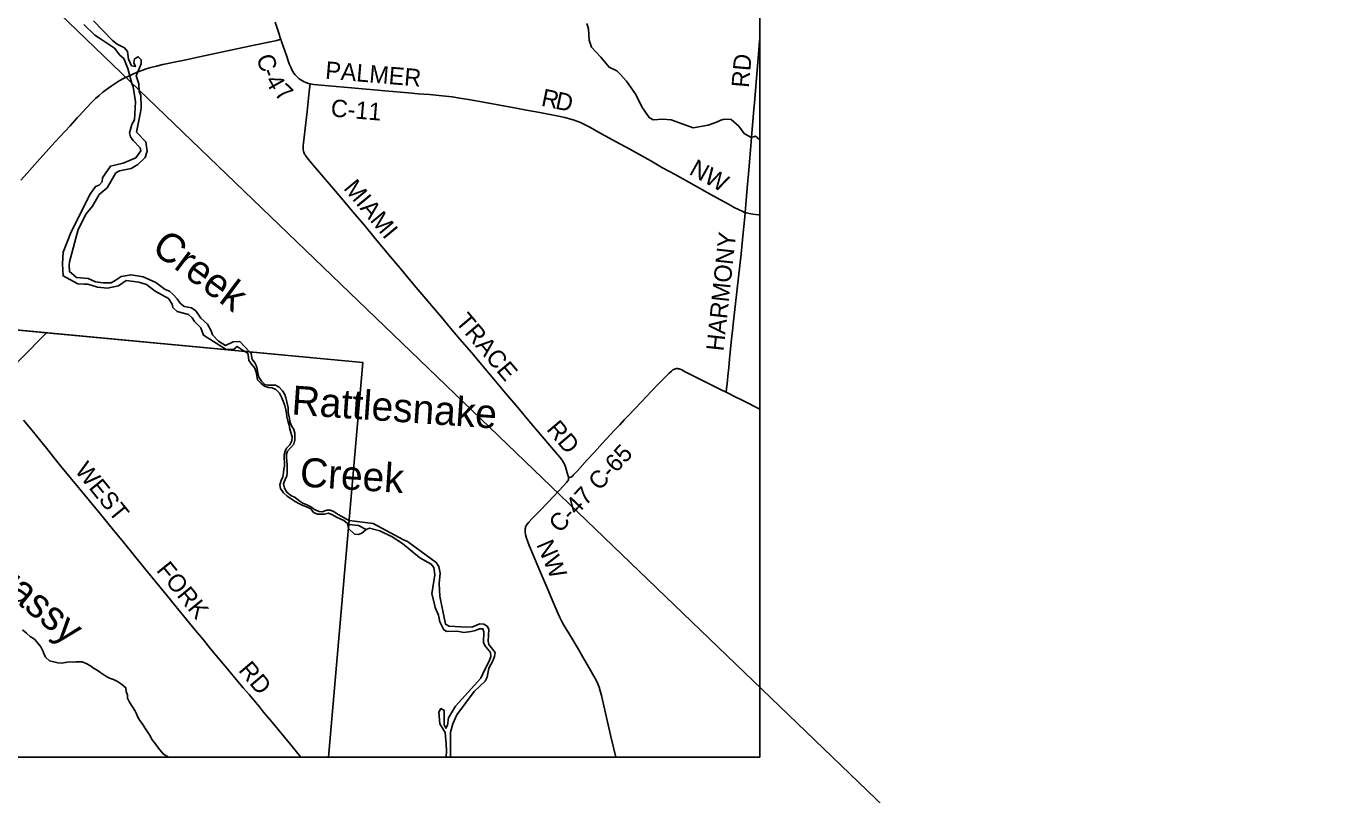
# Model space of a CAD drawing. Extents: x -49 to -8.2, y 9.4 to 23.5.
# Drawn here: x -40.683 to -38.56, y 14.142 to 15.394 of the extents above; entities that cross this region are included whole.
import ezdxf

# ---------------------------------------------------------------- set-up
doc = ezdxf.new("R2010")
doc.units = 0
for name, color, linetype in [('GM_X_Adjacent_County', 7, 'Continuous'), ('GM_X_County_Road', 7, 'Continuous'), ('GM_X_County_Road_Text', 7, 'Continuous'), ('GM_X_Major_River', 7, 'Continuous'), ('GM_X_Major_River_Text', 7, 'Continuous'), ('GM_X_Minor_River', 7, 'Continuous'), ('GM_X_Minor_River_Text', 7, 'Continuous'), ('GM_X_State_Route', 7, 'Continuous'), ('GM_X_Township', 7, 'Continuous'), ('GM_X_Township_Road', 7, 'Continuous'), ('GM_X_Township_Road_Text', 7, 'Continuous'), ('SC_Scratch1', 7, 'Continuous')]:
    doc.layers.add(name, color=color, linetype=linetype)

msp = doc.modelspace()

# ---------------------------------------------------------------- linework, layer by layer
at = {"layer": 'GM_X_Adjacent_County'}
for points in [[(-39.4895, 17.0861), (-39.4895, 14.2039), (-46.2895, 14.2039), (-46.2895, 15.4273)], [(-40.1912, 14.2039), (-40.1354, 14.8465), (-42.6345, 15.0821)]]:
    msp.add_lwpolyline(points, dxfattribs=at)
at = {"layer": 'GM_X_County_Road'}
for points in [[(-40.2687, 15.3724), (-40.2683, 15.3713), (-40.2676, 15.3693), (-40.2596, 15.3461), (-40.255, 15.3329), (-40.2526, 15.3271), (-40.2506, 15.3229), (-40.2491, 15.3201), (-40.2474, 15.3175), (-40.2455, 15.315), (-40.2434, 15.3126), (-40.2411, 15.3105), (-40.2387, 15.3085), (-40.2362, 15.3067), (-40.2335, 15.3051), (-40.2307, 15.3037), (-40.2278, 15.3025), (-40.2238, 15.3008), (-40.221, 15.3)], [(-39.5133, 15.0908), (-39.5121, 15.1038), (-39.5098, 15.1301), (-39.5075, 15.1595), (-39.5059, 15.1797), (-39.5037, 15.206), (-39.5025, 15.2199), (-39.5014, 15.2323), (-39.4995, 15.2524), (-39.4976, 15.2756), (-39.496, 15.2958), (-39.4915, 15.3484), (-39.4897, 15.3701), (-39.4895, 15.3725)], [(-40.221, 15.3), (-40.2224, 15.2876), (-40.226, 15.2552), (-40.228, 15.2367), (-40.2318, 15.2043), (-40.2323, 15.1996), (-40.2324, 15.1964), (-40.2322, 15.1933), (-40.2317, 15.1902), (-40.2312, 15.1887), (-40.23, 15.1858), (-40.2293, 15.1844), (-40.2275, 15.1818), (-40.2237, 15.1768), (-40.2156, 15.1673), (-40.1862, 15.1332), (-40.1671, 15.1107), (-40.1542, 15.0952), (-40.1312, 15.0678), (-40.1173, 15.0511), (-40.0933, 15.0225), (-40.0744, 14.9999), (-40.0646, 14.9879), (-40.0546, 14.9759), (-40.0426, 14.9617), (-40.0075, 14.9201), (-39.9924, 14.9023), (-39.9773, 14.8846), (-39.9582, 14.8621), (-39.9422, 14.8431), (-39.9223, 14.8192), (-39.9033, 14.7967), (-39.8832, 14.773), (-39.8651, 14.7516), (-39.84, 14.722), (-39.8218, 14.7007), (-39.8149, 14.6924), (-39.8111, 14.6875), (-39.8086, 14.6836), (-39.8079, 14.6823), (-39.8066, 14.6795), (-39.8055, 14.6766), (-39.8015, 14.6632), (-39.8008, 14.6602), (-39.8006, 14.6587), (-39.8006, 14.6585)], [(-40.221, 15.3), (-40.2182, 15.2995), (-40.2148, 15.2992), (-40.1909, 15.2969), (-40.1538, 15.2938), (-40.0996, 15.289), (-40.0609, 15.2854), (-40.0455, 15.2841), (-40.0269, 15.2826), (-40.0006, 15.28), (-39.9898, 15.2789), (-39.9774, 15.2771), (-39.9636, 15.2749), (-39.9392, 15.2704), (-39.8857, 15.2604), (-39.8689, 15.2573), (-39.8475, 15.2534), (-39.817, 15.2475), (-39.8064, 15.2452), (-39.7988, 15.2433), (-39.7929, 15.2415), (-39.787, 15.2394), (-39.7812, 15.237), (-39.7756, 15.2344), (-39.7673, 15.23), (-39.7468, 15.2189), (-39.7183, 15.2031), (-39.706, 15.1964), (-39.6666, 15.1746), (-39.6477, 15.1637), (-39.6273, 15.1525), (-39.5961, 15.1351), (-39.5663, 15.1184), (-39.5405, 15.1041), (-39.5309, 15.0989), (-39.524, 15.0954), (-39.517, 15.0922), (-39.5141, 15.091), (-39.5133, 15.0908)], [(-39.5443, 14.7982), (-39.5436, 14.8041), (-39.5428, 14.8118), (-39.5416, 14.8242), (-39.54, 14.8381), (-39.5386, 14.852), (-39.537, 14.869), (-39.5353, 14.8844), (-39.5337, 14.8983), (-39.5321, 14.9138), (-39.5264, 14.9663), (-39.5199, 15.0234), (-39.5164, 15.0574), (-39.5153, 15.0682), (-39.5139, 15.0837), (-39.5133, 15.0908)], [(-39.5133, 15.0908), (-39.5112, 15.0901), (-39.5067, 15.089), (-39.5006, 15.088), (-39.4914, 15.0868), (-39.4895, 15.0866)], [(-39.8006, 14.6585), (-39.7988, 14.6591), (-39.7971, 14.6597), (-39.7957, 14.6604), (-39.7949, 14.6611), (-39.7931, 14.663), (-39.7868, 14.6698), (-39.7701, 14.6882), (-39.7584, 14.7007), (-39.7458, 14.7144), (-39.7257, 14.7361), (-39.7173, 14.7452), (-39.7099, 14.7531), (-39.7034, 14.7599), (-39.6917, 14.7723), (-39.6735, 14.7915), (-39.666, 14.7994), (-39.6541, 14.8116), (-39.6455, 14.8206), (-39.6367, 14.8294), (-39.6332, 14.8325), (-39.6308, 14.8344), (-39.6294, 14.8352), (-39.628, 14.8359), (-39.6266, 14.8363), (-39.6251, 14.8366), (-39.6235, 14.8366), (-39.622, 14.8364), (-39.6205, 14.836), (-39.619, 14.8355), (-39.6162, 14.8343), (-39.612, 14.8321), (-39.5968, 14.8244), (-39.5718, 14.8118), (-39.5523, 14.8022), (-39.5443, 14.7982)], [(-39.5443, 14.7982), (-39.5411, 14.7967), (-39.5315, 14.7916), (-39.5162, 14.784), (-39.4895, 14.7707)], [(-39.8006, 14.6585), (-39.8005, 14.6573), (-39.8008, 14.6559), (-39.8013, 14.6546), (-39.8021, 14.6533), (-39.804, 14.6509), (-39.8083, 14.6464), (-39.8339, 14.6193), (-39.8478, 14.6046), (-39.8597, 14.5924), (-39.865, 14.5867), (-39.868, 14.5831), (-39.8689, 14.5818), (-39.8697, 14.5804), (-39.8704, 14.5789), (-39.8709, 14.5774), (-39.8712, 14.5758), (-39.8714, 14.5742), (-39.8714, 14.5727), (-39.8713, 14.5711), (-39.8711, 14.5695), (-39.8704, 14.5664), (-39.8688, 14.5604), (-39.8669, 14.5544), (-39.8648, 14.5486), (-39.8588, 14.5342), (-39.8472, 14.5071), (-39.8338, 14.4756), (-39.8271, 14.4599), (-39.8193, 14.4413), (-39.8149, 14.4313), (-39.8121, 14.4257), (-39.8083, 14.4189), (-39.7955, 14.3976), (-39.7852, 14.3803), (-39.7758, 14.3642), (-39.7663, 14.3481), (-39.7594, 14.336), (-39.7558, 14.3291), (-39.7532, 14.3235), (-39.751, 14.3177), (-39.7492, 14.3118), (-39.7472, 14.3043), (-39.7405, 14.2756), (-39.7318, 14.2377), (-39.7239, 14.2039)]]:
    msp.add_lwpolyline(points, dxfattribs=at)
at = {"layer": 'GM_X_Major_River'}
for p, q in [((-40.3195, 14.864), (-40.3282, 14.8648)), ((-40.1574, 14.5892), (-40.1585, 14.576)), ((-40.1579, 14.5829), (-40.1574, 14.5892))]:
    msp.add_line(p, q, dxfattribs=at)
for points in [[(-40.5894, 15.397), (-40.5713, 15.3795), (-40.5636, 15.3746), (-40.5391, 15.3582), (-40.5305, 15.3469), (-40.5242, 15.3414), (-40.5174, 15.3252), (-40.5111, 15.3006), (-40.5089, 15.2954), (-40.5052, 15.2709), (-40.5066, 15.2414), (-40.5113, 15.2339), (-40.5147, 15.2205), (-40.5131, 15.214), (-40.5092, 15.2077), (-40.4976, 15.1959), (-40.4962, 15.1911), (-40.5047, 15.1795), (-40.5254, 15.1709), (-40.546, 15.1659), (-40.5546, 15.1537), (-40.5587, 15.1472), (-40.5595, 15.1407), (-40.5642, 15.1353), (-40.5703, 15.1329), (-40.5789, 15.1204), (-40.6099, 15.0592), (-40.6226, 15.0259), (-40.624, 15.007), (-40.6229, 14.9876), (-40.6059, 14.9786), (-40.5989, 14.9745), (-40.5885, 14.9739), (-40.5829, 14.974), (-40.5672, 14.9694), (-40.5509, 14.9674), (-40.533, 14.9715), (-40.5203, 14.9802), (-40.4996, 14.9772), (-40.4873, 14.9736), (-40.4732, 14.9629), (-40.4512, 14.9507), (-40.4453, 14.9415), (-40.4444, 14.9362), (-40.4371, 14.9298), (-40.4191, 14.9244), (-40.4131, 14.919)], [(-40.4441, 14.9571), (-40.4499, 14.9627), (-40.4569, 14.9653), (-40.4721, 14.9769), (-40.4926, 14.9862), (-40.5124, 14.9895), (-40.5282, 14.9866), (-40.538, 14.9801), (-40.5449, 14.9762), (-40.5576, 14.9761), (-40.5703, 14.978), (-40.5822, 14.9833), (-40.6014, 14.985), (-40.6126, 14.9944), (-40.613, 15.0051), (-40.6124, 15.0104), (-40.5982, 15.0633), (-40.5853, 15.0884), (-40.575, 15.1013), (-40.5642, 15.1199), (-40.5515, 15.1311), (-40.5374, 15.1552), (-40.5311, 15.1585), (-40.5122, 15.1623), (-40.5011, 15.1688), (-40.4895, 15.1804), (-40.4859, 15.1906), (-40.4882, 15.2056), (-40.5033, 15.2213), (-40.4965, 15.2567), (-40.496, 15.2623), (-40.4966, 15.2815), (-40.499, 15.2877), (-40.4999, 15.3), (-40.5039, 15.3134), (-40.4958, 15.333), (-40.4961, 15.3393), (-40.5007, 15.3443), (-40.5069, 15.3408), (-40.5076, 15.3343), (-40.5054, 15.3282), (-40.5114, 15.3296), (-40.5168, 15.3402), (-40.5179, 15.3529), (-40.5233, 15.3591), (-40.5348, 15.3648), (-40.5423, 15.371), (-40.5737, 15.4027)], [(-40.3195, 14.864), (-40.3352, 14.8806), (-40.3461, 14.8801), (-40.3585, 14.874), (-40.37, 14.881), (-40.3801, 14.8913), (-40.3819, 14.8979), (-40.3878, 14.9089), (-40.3991, 14.9187), (-40.4072, 14.9305), (-40.4138, 14.9357), (-40.4261, 14.9376), (-40.4325, 14.943), (-40.4371, 14.9503), (-40.4441, 14.9571)], [(-40.4131, 14.919), (-40.409, 14.913), (-40.3991, 14.9028), (-40.3944, 14.8909), (-40.3579, 14.8675), (-40.3453, 14.8681), (-40.3397, 14.8727), (-40.3282, 14.8648)], [(-40.3282, 14.8648), (-40.3224, 14.8615), (-40.3215, 14.8549), (-40.3206, 14.85), (-40.3161, 14.8435), (-40.3109, 14.8375), (-40.3087, 14.8305), (-40.308, 14.8246), (-40.3068, 14.8183), (-40.3012, 14.8131), (-40.2953, 14.8078), (-40.2889, 14.806), (-40.2828, 14.8052), (-40.2766, 14.8023), (-40.2709, 14.7963), (-40.2672, 14.7892), (-40.2647, 14.7833), (-40.2621, 14.7764), (-40.2605, 14.7694), (-40.2596, 14.7642), (-40.2587, 14.7579), (-40.2575, 14.7515), (-40.2553, 14.7444), (-40.2543, 14.7387), (-40.2522, 14.7324), (-40.2504, 14.7253), (-40.2509, 14.7187), (-40.2539, 14.7123), (-40.2597, 14.707), (-40.2614, 14.7019), (-40.2631, 14.6959), (-40.2633, 14.6909), (-40.2628, 14.6841), (-40.2625, 14.6778), (-40.2636, 14.6729), (-40.2644, 14.667), (-40.2657, 14.6606), (-40.2682, 14.6545), (-40.2702, 14.6474), (-40.269, 14.6411), (-40.2645, 14.6345), (-40.2583, 14.629), (-40.2519, 14.6243), (-40.2455, 14.6202), (-40.2393, 14.6167), (-40.233, 14.6138), (-40.227, 14.6116), (-40.2201, 14.6081), (-40.2153, 14.6021), (-40.2092, 14.5996), (-40.2026, 14.5993), (-40.1976, 14.5998), (-40.1913, 14.6012), (-40.1845, 14.5985), (-40.1781, 14.5944), (-40.1722, 14.5918), (-40.166, 14.5893), (-40.1602, 14.5841), (-40.1579, 14.5829)], [(-40.3282, 14.8648), (-40.3195, 14.864)], [(-40.1574, 14.5892), (-40.1627, 14.5919), (-40.1693, 14.596), (-40.1754, 14.5991), (-40.1818, 14.6034), (-40.1878, 14.6061), (-40.1941, 14.6058), (-40.2016, 14.6031), (-40.2065, 14.6037), (-40.2137, 14.6072), (-40.2197, 14.6117), (-40.2265, 14.6148), (-40.233, 14.6174), (-40.2394, 14.6217), (-40.2456, 14.6265), (-40.2522, 14.6298), (-40.2588, 14.6352), (-40.2629, 14.6417), (-40.2645, 14.649), (-40.2615, 14.6558), (-40.2592, 14.662), (-40.2585, 14.6671), (-40.2583, 14.6797), (-40.259, 14.6856), (-40.2595, 14.6905), (-40.2594, 14.697), (-40.2578, 14.7021), (-40.2522, 14.7079), (-40.2478, 14.7133), (-40.2461, 14.72), (-40.2457, 14.7262), (-40.2458, 14.7312), (-40.2476, 14.7375), (-40.2517, 14.7442), (-40.2541, 14.7503), (-40.2548, 14.7552), (-40.256, 14.7623), (-40.2565, 14.7672), (-40.257, 14.7725), (-40.2581, 14.7775), (-40.259, 14.7824), (-40.2606, 14.7891), (-40.2624, 14.7943), (-40.2659, 14.8004), (-40.2716, 14.8064), (-40.2776, 14.8095), (-40.2898, 14.8097), (-40.2945, 14.8109), (-40.3, 14.8161), (-40.3043, 14.8226), (-40.3059, 14.8297), (-40.3073, 14.8358), (-40.3084, 14.8407), (-40.3112, 14.8459), (-40.3156, 14.8518), (-40.3165, 14.8575), (-40.3172, 14.8623), (-40.3195, 14.864)], [(-39.9928, 14.2039), (-39.9925, 14.2448), (-39.9889, 14.2582), (-39.9822, 14.2727), (-39.9542, 14.3108), (-39.9365, 14.3278), (-39.9329, 14.3342), (-39.9304, 14.3486), (-39.9236, 14.361), (-39.9208, 14.3676), (-39.9201, 14.3742), (-39.9302, 14.3873), (-39.9312, 14.393), (-39.9305, 14.4123), (-39.9329, 14.4171), (-39.9386, 14.4204), (-39.9448, 14.4209), (-39.958, 14.4153), (-39.9761, 14.416), (-39.9949, 14.417), (-40.0007, 14.4203), (-40.0102, 14.4661), (-40.0109, 14.4866), (-40.0093, 14.5033), (-40.0117, 14.5145), (-40.0158, 14.5208), (-40.0624, 14.5548), (-40.0692, 14.558), (-40.1186, 14.5843), (-40.1574, 14.5892)], [(-40.1585, 14.576), (-40.1489, 14.5671), (-40.1423, 14.5666), (-40.1369, 14.5688), (-40.13, 14.5748), (-40.1246, 14.577), (-40.1076, 14.5725), (-40.0878, 14.5627), (-40.071, 14.5518), (-40.0423, 14.5285), (-40.024, 14.5183), (-40.0196, 14.5127), (-40.018, 14.5009), (-40.0229, 14.4701), (-40.0188, 14.4529), (-40.0174, 14.4478), (-40.0123, 14.435), (-40.0098, 14.4241), (-40.0035, 14.4113), (-39.9984, 14.4084), (-39.9817, 14.4088), (-39.9711, 14.4071), (-39.9591, 14.4085), (-39.9522, 14.4104), (-39.9459, 14.4128), (-39.9398, 14.4131), (-39.9384, 14.4081), (-39.939, 14.3907), (-39.937, 14.3855), (-39.9277, 14.3745), (-39.9269, 14.368), (-39.9291, 14.3618), (-39.9403, 14.3394), (-39.9434, 14.3323), (-39.9844, 14.287)], [(-39.9844, 14.287), (-39.9958, 14.2682), (-39.9975, 14.2559), (-40.0002, 14.251), (-40.0028, 14.2567), (-40.003, 14.2801), (-40.0083, 14.283), (-40.0114, 14.277), (-40.0102, 14.2582), (-40.0015, 14.2442), (-40.0002, 14.2316), (-39.9999, 14.2256), (-39.9989, 14.214), (-39.9999, 14.2039)]]:
    msp.add_lwpolyline(points, dxfattribs=at)
at = {"layer": 'GM_X_Minor_River'}
msp.add_line((-40.3282, 14.8648), (-40.3195, 14.864), dxfattribs=at)
for points in [[(-39.4895, 15.209), (-39.4967, 15.2149), (-39.5034, 15.2131), (-39.5151, 15.2192), (-39.5236, 15.2311), (-39.5358, 15.2419), (-39.5474, 15.2427), (-39.5527, 15.2409), (-39.5598, 15.2378), (-39.5734, 15.2327), (-39.598, 15.2285), (-39.6339, 15.2417), (-39.647, 15.2428), (-39.6628, 15.2414), (-39.6694, 15.2453), (-39.6811, 15.263), (-39.6912, 15.2831), (-39.7063, 15.3044), (-39.7165, 15.3162), (-39.7218, 15.3214), (-39.7346, 15.3271), (-39.7478, 15.3438), (-39.7635, 15.3601), (-39.7671, 15.3713), (-39.768, 15.3896), (-39.7709, 15.3982)], [(-40.1601, 14.584), (-40.1599, 14.5819), (-40.1593, 14.5782), (-40.1585, 14.576)], [(-40.1579, 14.5829), (-40.1426, 14.5811), (-40.13, 14.5748)], [(-40.6826, 14.4057), (-40.6888, 14.4113)], [(-40.4516, 14.2039), (-40.4542, 14.2053), (-40.4597, 14.2086), (-40.4655, 14.2157), (-40.4694, 14.2209), (-40.4731, 14.2259), (-40.478, 14.2322), (-40.4824, 14.2401), (-40.4854, 14.2449), (-40.4899, 14.2514), (-40.4943, 14.2587), (-40.4979, 14.2635), (-40.5012, 14.269), (-40.5033, 14.2742), (-40.506, 14.2801), (-40.5099, 14.2861), (-40.515, 14.2932), (-40.5181, 14.2999), (-40.518, 14.3046), (-40.5201, 14.3109), (-40.5211, 14.3168), (-40.5277, 14.3226), (-40.5343, 14.3271), (-40.5411, 14.3304), (-40.5475, 14.3324), (-40.5549, 14.3369), (-40.5613, 14.3411), (-40.5675, 14.3456), (-40.5736, 14.3489), (-40.5785, 14.3524), (-40.5853, 14.3565), (-40.5921, 14.359), (-40.597, 14.3591), (-40.6022, 14.359), (-40.6081, 14.3587), (-40.6128, 14.3589), (-40.6193, 14.3581), (-40.6258, 14.357), (-40.6313, 14.3577), (-40.6381, 14.3589), (-40.6452, 14.3609), (-40.6514, 14.3665), (-40.6536, 14.3715), (-40.6563, 14.3782), (-40.6589, 14.3833), (-40.6638, 14.3893), (-40.6696, 14.3958), (-40.6764, 14.4005), (-40.6826, 14.4057)]]:
    msp.add_lwpolyline(points, dxfattribs=at)
at = {"layer": 'GM_X_State_Route'}
for points in [[(-40.437, 15.3365), (-40.4255, 15.3389), (-40.4012, 15.3441), (-40.3709, 15.3505), (-40.3147, 15.3626), (-40.2828, 15.3693), (-40.2752, 15.3709), (-40.2722, 15.3716), (-40.2708, 15.3719), (-40.2687, 15.3724), (-40.2701, 15.3766), (-40.271, 15.3794), (-40.2726, 15.3845), (-40.2752, 15.3924), (-40.2781, 15.4009)], [(-40.5968, 15.2483), (-40.5845, 15.2618), (-40.5769, 15.2697), (-40.5702, 15.2762), (-40.5644, 15.2814), (-40.5584, 15.2864), (-40.5523, 15.2911), (-40.5447, 15.2966), (-40.5382, 15.3009), (-40.5316, 15.3049), (-40.5248, 15.3087), (-40.5178, 15.3123), (-40.5094, 15.3162), (-40.5022, 15.3192), (-40.4949, 15.322), (-40.4876, 15.3245), (-40.4801, 15.3267), (-40.4711, 15.3291), (-40.4605, 15.3315), (-40.437, 15.3365)], [(-40.6919, 15.1433), (-40.6815, 15.1549), (-40.6609, 15.1781), (-40.6359, 15.2058), (-40.6117, 15.2321), (-40.6002, 15.2447), (-40.5968, 15.2483)]]:
    msp.add_lwpolyline(points, dxfattribs=at)
at = {"layer": 'GM_X_Township'}
msp.add_line((-41.6759, 14.2039), (-40.1912, 14.2039), dxfattribs=at)
for points in [[(-40.8503, 14.9138), (-40.6501, 14.895), (-40.1354, 14.8465), (-40.1912, 14.2039), (-39.4895, 14.2039), (-39.4895, 17.0861)], [(-41.6759, 14.2039), (-41.4369, 14.3413), (-41.4231, 14.3535), (-41.3209, 14.4444), (-41.2078, 14.512), (-40.9525, 14.6647), (-40.8419, 14.7281), (-40.7347, 14.8098), (-40.6501, 14.895), (-40.8503, 14.9138), (-41.0499, 14.9326), (-41.3564, 14.9614), (-41.4287, 14.9682), (-42.3443, 15.0547), (-42.5793, 15.0769), (-42.6345, 15.0821), (-43.168, 15.1318), (-43.3434, 15.1483), (-43.7172, 15.1832), (-43.8792, 15.1984), (-44.0636, 15.2153), (-44.1589, 15.0879), (-44.8206, 14.2039)], [(-40.1912, 14.2039), (-40.1354, 14.8465), (-40.6501, 14.895), (-40.7347, 14.8098), (-40.8419, 14.7281), (-40.9525, 14.6647), (-41.2078, 14.512), (-41.3209, 14.4444), (-41.4231, 14.3535), (-41.4369, 14.3413), (-41.6759, 14.2039)]]:
    msp.add_lwpolyline(points, dxfattribs=at)
at = {"layer": 'GM_X_Township_Road'}
msp.add_lwpolyline([(-40.2362, 14.2039), (-40.2526, 14.224), (-40.2834, 14.2614), (-40.2967, 14.2774), (-40.3034, 14.2856), (-40.3125, 14.2966), (-40.3204, 14.3058), (-40.3299, 14.3168), (-40.3415, 14.3303), (-40.354, 14.3453), (-40.383, 14.3805), (-40.3946, 14.3947), (-40.4073, 14.4101), (-40.4366, 14.4459), (-40.4555, 14.4689), (-40.4656, 14.4812), (-40.4854, 14.5055), (-40.5066, 14.5315), (-40.5249, 14.5538), (-40.5411, 14.5735), (-40.5644, 14.6022), (-40.6269, 14.6783), (-40.6379, 14.6918), (-40.6457, 14.7015), (-40.6593, 14.7184), (-40.6732, 14.7356), (-40.6871, 14.7527)], dxfattribs=at)
at = {"layer": 'SC_Scratch1'}
msp.add_line((-49.0354, 23.5097), (-36.4374, 11.3792), dxfattribs=at)

# ---------------------------------------------------------------- texts
at = {"layer": 'GM_X_County_Road_Text'}
for s, height, rotation, p in [('C', 0.0284, 289.3116, (-40.3091, 15.343)), ('PALMER', 0.02841, 355.1531, (-40.1972, 15.3087)), ('RD', 0.02841, 85.0738, (-39.5073, 15.2931)), ('-', 0.0284, 291.165, (-40.3011, 15.3202)), ('4', 0.0284, 299.2462, (-40.2951, 15.3055)), ('7', 0.0284, 316.5767, (-40.2809, 15.2829)), ('R', 0.0284, 348.2316, (-39.8464, 15.2648)), ('D', 0.0284, 348.1828, (-39.8235, 15.26)), ('C-11', 0.02841, 355.208, (-40.1882, 15.2471)), ('NW', 0.02841, 330.865, (-39.6061, 15.154)), ('MIAMI', 0.02841, 309.6675, (-40.1679, 15.1297)), ('HARMONY', 0.02841, 83.908, (-39.5485, 14.8641)), ('TRACE', 0.02841, 310.151, (-39.9859, 14.9122)), ('RD', 0.02841, 310.187, (-39.8377, 14.7373)), ('C-65', 0.02841, 47.1747, (-39.7504, 14.6364)), ('C-47', 0.02841, 46.9076, (-39.8148, 14.5675)), ('NW', 0.02841, 293.0877, (-39.8533, 14.5502))]:
    msp.add_text(s, height=height, rotation=rotation, dxfattribs=at).set_placement(p)
at = {"layer": 'GM_X_Major_River_Text'}
for s, height, rotation, p in [('Creek', 0.04735, 323.2081, (-40.4812, 15.0283)), ('Rattlesnake', 0.047347, 356.0429, (-40.2522, 14.7619)), ('Creek', 0.04735, 356.3167, (-40.2387, 14.6447))]:
    msp.add_text(s, height=height, rotation=rotation, dxfattribs=at).set_placement(p)
at = {"layer": 'GM_X_Minor_River_Text'}
msp.add_text('Grassy', height=0.04735, rotation=320.3045, dxfattribs=at).set_placement((-40.7693, 14.5132))
at = {"layer": 'GM_X_Township_Road_Text'}
for s, rotation, p in [('WEST', 309.1296, (-40.605, 14.6702)), ('FORK', 309.1179, (-40.4723, 14.5079)), ('RD', 310.3448, (-40.3389, 14.3449))]:
    msp.add_text(s, height=0.02841, rotation=rotation, dxfattribs=at).set_placement(p)

doc.saveas('drawing.dxf')
